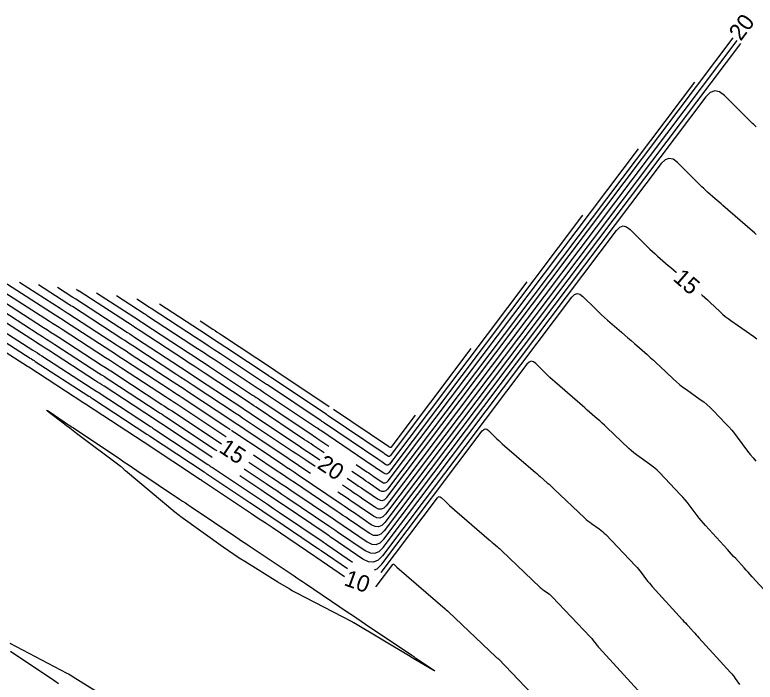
# Model space of a CAD drawing. Extents: x 1797789 to 1803805, y 249066 to 250293.
# Drawn here: x 1798010.2 to 1798279.1, y 250027.1 to 250269.4 of the extents above; entities that cross this region are included whole.
import ezdxf

# ---------------------------------------------------------------- set-up
doc = ezdxf.new("R2010")
doc.units = 0
doc.layers.add('33', color=7, linetype='Continuous')
doc.layers.add('34', color=7, linetype='Continuous')

msp = doc.modelspace()

# ---------------------------------------------------------------- linework, layer by layer
at = {"layer": '33'}
for points in [[(1798130.87, 250101.08), (1798134.09, 250098.91), (1798135.07, 250098.25), (1798136.05, 250097.58), (1798137.03, 250096.91), (1798138.01, 250096.25), (1798141.93, 250093.57), (1798142.88, 250093.11), (1798143.76, 250093.04), (1798144.57, 250093.38), (1798145.32, 250094.13), (1798271.14, 250260.98)], [(1798095.22, 250106.98), (1798103.53, 250101.42), (1798105.25, 250100.27), (1798106.97, 250099.12), (1798108.69, 250097.96), (1798110.41, 250096.8), (1798125.95, 250086.31), (1798126.82, 250085.72), (1798127.69, 250085.13), (1798128.56, 250084.54), (1798129.43, 250083.94), (1798138.14, 250078), (1798139.82, 250077.17), (1798141.39, 250077.06), (1798142.83, 250077.67), (1798144.16, 250078.99), (1798228.7, 250191.09), (1798229.87, 250192.25), (1798231.09, 250192.7), (1798232.36, 250192.43), (1798233.68, 250191.44), (1798239.95, 250185.17), (1798240.85, 250184.28), (1798241.78, 250183.41), (1798242.71, 250182.55), (1798243.66, 250181.72), (1798247.5, 250178.4), (1798248.46, 250177.57), (1798249.42, 250176.74), (1798250.38, 250175.9), (1798250.53, 250175.77)], [(1797989.59, 250175.67), (1798000.85, 250168.54), (1798001.61, 250168.05), (1798002.37, 250167.57), (1798003.13, 250167.08), (1798003.89, 250166.6), (1798020.62, 250155.88), (1798022.02, 250154.98), (1798023.42, 250154.08), (1798024.82, 250153.18), (1798026.22, 250152.27), (1798041.96, 250142.08), (1798043.19, 250141.29), (1798044.41, 250140.49), (1798045.64, 250139.69), (1798046.86, 250138.89), (1798063.61, 250127.93), (1798064.47, 250127.36), (1798065.33, 250126.8), (1798066.19, 250126.23), (1798067.05, 250125.67), (1798084.43, 250114.17), (1798085.23, 250113.64)], [(1798025.68, 250170.44), (1798031.26, 250166.87), (1798031.52, 250166.7), (1798031.79, 250166.53), (1798032.05, 250166.36), (1798032.32, 250166.19), (1798051.11, 250154.02), (1798051.94, 250153.48), (1798052.77, 250152.94), (1798053.6, 250152.4), (1798054.43, 250151.86), (1798070.42, 250141.4), (1798072.05, 250140.33), (1798073.69, 250139.25), (1798075.33, 250138.17), (1798076.96, 250137.09), (1798092.6, 250126.75), (1798093.58, 250126.11), (1798094.55, 250125.46), (1798095.52, 250124.82), (1798096.49, 250124.17), (1798113.46, 250112.83), (1798114.4, 250112.2), (1798115.33, 250111.57), (1798116.27, 250110.94), (1798117.21, 250110.31), (1798120.93, 250107.8)], [(1798259.56, 250167.87), (1798259.87, 250167.6), (1798260.81, 250166.75), (1798261.74, 250165.89), (1798262.66, 250165.03), (1798266.33, 250161.54), (1798267.26, 250160.69), (1798268.22, 250159.87), (1798269.21, 250159.09), (1798270.24, 250158.35), (1798278.62, 250152.51), (1798279.62, 250151.77)], [(1798175.84, 250148.21), (1798146.48, 250109.27), (1798146.31, 250109.1), (1798146.13, 250109.03), (1798145.93, 250109.04), (1798145.72, 250109.14), (1798144.85, 250109.74), (1798144.63, 250109.89), (1798144.41, 250110.04), (1798144.2, 250110.18), (1798143.98, 250110.33), (1798124, 250123.82), (1798123.85, 250123.92), (1798123.7, 250124.03), (1798123.54, 250124.13), (1798123.39, 250124.23), (1798103.3, 250137.66), (1798103.1, 250137.79), (1798102.91, 250137.92), (1798102.71, 250138.05), (1798102.52, 250138.18), (1798086.86, 250148.53), (1798084.46, 250150.12), (1798082.05, 250151.7), (1798079.65, 250153.28), (1798077.24, 250154.86), (1798062.79, 250164.32)], [(1797994.16, 250155.02), (1798014.86, 250141.76), (1798014.96, 250141.69), (1798015.06, 250141.63), (1798015.16, 250141.56), (1798015.26, 250141.5), (1798035.29, 250128.53), (1798035.86, 250128.16), (1798035.96, 250128.1), (1798036.05, 250128.04), (1798036.15, 250127.98), (1798036.24, 250127.91), (1798056.81, 250114.45), (1798056.89, 250114.4), (1798056.97, 250114.35), (1798057.05, 250114.29), (1798057.13, 250114.24), (1798077.64, 250100.68), (1798077.73, 250100.62), (1798077.83, 250100.56), (1798077.92, 250100.5), (1798078.01, 250100.44), (1798093.6, 250090.02), (1798096.1, 250088.34), (1798098.61, 250086.66), (1798101.11, 250084.98), (1798103.61, 250083.29), (1798119.15, 250072.8), (1798119.24, 250072.74), (1798119.33, 250072.68), (1798119.42, 250072.62), (1798119.51, 250072.55), (1798129.96, 250065.42)], [(1798141.38, 250061.72), (1798141.44, 250061.77), (1798147.47, 250069.77), (1798147.58, 250069.88), (1798147.69, 250069.92), (1798147.81, 250069.89), (1798147.93, 250069.8), (1798148.43, 250069.3), (1798148.56, 250069.18), (1798148.69, 250069.05), (1798148.82, 250068.93), (1798148.95, 250068.82), (1798166.46, 250053.69), (1798166.57, 250053.6), (1798166.68, 250053.5), (1798166.79, 250053.41), (1798166.9, 250053.31), (1798167.33, 250052.93), (1798167.44, 250052.84), (1798167.55, 250052.74), (1798167.65, 250052.64), (1798167.76, 250052.55), (1798184.95, 250036.21), (1798185.02, 250036.14), (1798185.1, 250036.08), (1798185.17, 250036.02), (1798185.25, 250035.96), (1798185.57, 250035.74), (1798185.65, 250035.68), (1798185.72, 250035.62), (1798185.79, 250035.56), (1798185.86, 250035.49), (1798202.79, 250017.7)]]:
    msp.add_lwpolyline(points, dxfattribs=at)
at = {"layer": '34'}
for points in [[(1798272.45, 250259.99), (1798145.09, 250091.1), (1798144.22, 250090.24), (1798143.28, 250089.85), (1798142.27, 250089.92), (1798141.17, 250090.46), (1798136.65, 250093.55), (1798135.51, 250094.32), (1798134.38, 250095.09), (1798133.24, 250095.86), (1798132.11, 250096.63), (1798129.19, 250098.6)], [(1798273.75, 250259), (1798144.86, 250088.07), (1798143.88, 250087.1), (1798142.81, 250086.65), (1798141.66, 250086.73), (1798140.42, 250087.34), (1798135.28, 250090.85), (1798133.99, 250091.72), (1798132.71, 250092.6), (1798131.42, 250093.47), (1798130.13, 250094.34), (1798127.51, 250096.11)], [(1798257, 250244.95), (1798145.55, 250097.16), (1798144.92, 250096.53), (1798144.23, 250096.24), (1798143.49, 250096.29), (1798142.69, 250096.69), (1798139.38, 250098.94), (1798138.55, 250099.51), (1798137.72, 250100.07), (1798136.9, 250100.63), (1798136.07, 250101.2), (1798132.55, 250103.57)], [(1798279.42, 250228.72), (1798278.98, 250229.12), (1798278.56, 250229.52), (1798278.14, 250229.93), (1798267.97, 250240.1), (1798266.18, 250241.44), (1798264.45, 250241.81), (1798262.78, 250241.2), (1798261.19, 250239.62), (1798144.63, 250085.05), (1798143.53, 250083.95), (1798142.34, 250083.45), (1798141.05, 250083.55), (1798139.66, 250084.23), (1798133.4, 250088.5), (1798132.22, 250089.3), (1798131.03, 250090.11), (1798129.85, 250090.91), (1798128.67, 250091.71), (1798113.13, 250102.2), (1798111.72, 250103.15), (1798110.32, 250104.1), (1798108.91, 250105.04), (1798107.5, 250105.99), (1798098.55, 250111.97)], [(1798134.23, 250106.06), (1798138.04, 250103.48), (1798138.72, 250103.02), (1798139.4, 250102.56), (1798140.07, 250102.1), (1798140.75, 250101.64), (1798143.45, 250099.8), (1798144.1, 250099.48), (1798144.71, 250099.44), (1798145.27, 250099.67), (1798145.78, 250100.18), (1798236.71, 250220.76)], [(1798279.47, 250189.56), (1798278.79, 250190.17), (1798278.11, 250190.78), (1798267.37, 250200.17), (1798266.67, 250200.78), (1798265.97, 250201.39), (1798265.27, 250201.99), (1798264.57, 250202.6), (1798261.76, 250205.03), (1798261.06, 250205.64), (1798260.38, 250206.26), (1798259.71, 250206.9), (1798259.04, 250207.55), (1798250.83, 250215.77), (1798249.27, 250216.93), (1798247.77, 250217.25), (1798246.33, 250216.73), (1798244.94, 250215.36), (1798144.39, 250082.02), (1798143.18, 250080.81), (1798141.86, 250080.26), (1798140.43, 250080.36), (1798138.9, 250081.11), (1798131.41, 250086.22), (1798130.39, 250086.92), (1798129.36, 250087.62), (1798128.34, 250088.31), (1798127.31, 250089.01), (1798111.77, 250099.5), (1798110.21, 250100.56), (1798108.64, 250101.61), (1798107.08, 250102.66), (1798105.51, 250103.7), (1798096.88, 250109.47)], [(1798216.42, 250196.58), (1798146.01, 250103.21), (1798145.62, 250102.82), (1798145.18, 250102.63), (1798144.71, 250102.67), (1798144.21, 250102.92), (1798142.12, 250104.34), (1798141.59, 250104.7), (1798141.07, 250105.05), (1798140.55, 250105.41), (1798140.02, 250105.76), (1798121.29, 250118.42), (1798120.82, 250118.73), (1798120.35, 250119.04), (1798119.88, 250119.36), (1798119.41, 250119.67), (1798100.57, 250132.26), (1798100.07, 250132.6), (1798099.56, 250132.94), (1798099.06, 250133.27), (1798098.55, 250133.61), (1798082.91, 250143.95), (1798080.81, 250145.34), (1798078.71, 250146.72), (1798076.6, 250148.1), (1798074.5, 250149.48), (1798058.43, 250160), (1798058.11, 250160.21), (1798057.79, 250160.42), (1798057.47, 250160.62), (1798057.15, 250160.83), (1798047.18, 250167.29)], [(1797981.95, 250176.97), (1797998.46, 250166.5), (1797999.58, 250165.79), (1798000.7, 250165.08), (1798001.81, 250164.37), (1798002.92, 250163.65), (1798018.72, 250153.54), (1798020.23, 250152.56), (1798021.75, 250151.59), (1798023.27, 250150.61), (1798024.78, 250149.63), (1798040.74, 250139.3), (1798041.74, 250138.65), (1798042.74, 250138), (1798043.74, 250137.35), (1798044.74, 250136.69), (1798062.25, 250125.23), (1798062.96, 250124.77), (1798063.66, 250124.31), (1798064.36, 250123.85), (1798065.07, 250123.38), (1798083.07, 250111.47), (1798083.57, 250111.15)], [(1798086.9, 250116.14), (1798086.82, 250116.19), (1798085.79, 250116.87), (1798069.03, 250127.95), (1798068.02, 250128.62), (1798067, 250129.29), (1798065.99, 250129.96), (1798064.97, 250130.62), (1798048.98, 250141.09), (1798047.53, 250142.03), (1798046.08, 250142.98), (1798044.63, 250143.92), (1798043.18, 250144.86), (1798027.44, 250155.06), (1798026.27, 250155.81), (1798025.1, 250156.57), (1798023.92, 250157.32), (1798022.75, 250158.07), (1798004.85, 250169.54), (1798004.45, 250169.8), (1798004.04, 250170.06), (1798003.64, 250170.32), (1798003.23, 250170.57), (1797997.24, 250174.38)], [(1798088.57, 250118.63), (1798088.34, 250118.78), (1798087.15, 250119.57), (1798071.02, 250130.24), (1798069.85, 250131.01), (1798068.68, 250131.78), (1798067.51, 250132.55), (1798066.33, 250133.32), (1798050.43, 250143.72), (1798049.09, 250144.6), (1798047.76, 250145.47), (1798046.42, 250146.34), (1798045.07, 250147.21), (1798028.66, 250157.84), (1798027.71, 250158.45), (1798026.77, 250159.06), (1798025.82, 250159.67), (1798024.88, 250160.27), (1798005.81, 250172.49), (1798005.76, 250172.52), (1798005.71, 250172.55), (1798005.67, 250172.58), (1798005.62, 250172.61), (1798004.88, 250173.08)], [(1798117.57, 250102.83), (1798114.49, 250104.91), (1798113.24, 250105.75), (1798111.99, 250106.59), (1798110.74, 250107.43), (1798109.48, 250108.27), (1798093.76, 250118.77), (1798092.48, 250119.63), (1798091.2, 250120.48), (1798089.92, 250121.33), (1798088.64, 250122.18), (1798073, 250132.52), (1798071.67, 250133.4), (1798070.35, 250134.27), (1798069.02, 250135.14), (1798067.69, 250136.01), (1798051.77, 250146.44), (1798050.6, 250147.2), (1798049.43, 250147.96), (1798048.26, 250148.72), (1798047.09, 250149.48), (1798029.88, 250160.62), (1798029.16, 250161.09), (1798028.44, 250161.55), (1798027.72, 250162.01), (1798027, 250162.47), (1798011.88, 250172.16)], [(1798119.25, 250105.31), (1798115.85, 250107.61), (1798114.75, 250108.35), (1798113.66, 250109.08), (1798112.57, 250109.81), (1798111.47, 250110.55), (1798095.12, 250121.47), (1798094, 250122.22), (1798092.87, 250122.97), (1798091.75, 250123.72), (1798090.62, 250124.46), (1798074.98, 250134.81), (1798073.5, 250135.78), (1798072.02, 250136.76), (1798070.54, 250137.73), (1798069.06, 250138.71), (1798053.1, 250149.15), (1798052.1, 250149.8), (1798051.1, 250150.45), (1798050.1, 250151.1), (1798049.1, 250151.75), (1798031.1, 250163.41), (1798030.6, 250163.73), (1798030.11, 250164.04), (1798029.62, 250164.36), (1798029.13, 250164.67), (1798018.78, 250171.3)], [(1798196.13, 250172.39), (1798146.25, 250106.24), (1798145.96, 250105.96), (1798145.66, 250105.83), (1798145.32, 250105.85), (1798144.96, 250106.03), (1798143.48, 250107.04), (1798143.11, 250107.29), (1798142.74, 250107.55), (1798142.37, 250107.8), (1798142, 250108.05), (1798122.65, 250121.12), (1798122.33, 250121.33), (1798122.02, 250121.54), (1798121.71, 250121.74), (1798121.4, 250121.95), (1798101.94, 250134.96), (1798101.59, 250135.19), (1798101.24, 250135.43), (1798100.89, 250135.66), (1798100.54, 250135.89), (1798084.9, 250146.23), (1798082.64, 250147.72), (1798080.38, 250149.21), (1798078.12, 250150.7), (1798075.86, 250152.18), (1798059.76, 250162.71), (1798059.61, 250162.81), (1798059.46, 250162.91), (1798059.31, 250163), (1798059.17, 250163.1), (1798054.52, 250166.11)], [(1798122.6, 250110.28), (1798118.57, 250113.01), (1798117.79, 250113.54), (1798117.01, 250114.06), (1798116.22, 250114.59), (1798115.44, 250115.11), (1798097.85, 250126.87), (1798097.03, 250127.41), (1798096.22, 250127.95), (1798095.4, 250128.49), (1798094.59, 250129.04), (1798078.95, 250139.38), (1798077.16, 250140.56), (1798075.36, 250141.74), (1798073.57, 250142.92), (1798071.78, 250144.1), (1798055.76, 250154.57), (1798055.1, 250155), (1798054.45, 250155.43), (1798053.79, 250155.86), (1798053.13, 250156.29), (1798033.53, 250168.98), (1798033.5, 250169), (1798033.46, 250169.02), (1798033.42, 250169.05), (1798033.38, 250169.07), (1798032.58, 250169.59)], [(1798039.85, 250168.46), (1798055.14, 250158.56), (1798055.63, 250158.24), (1798056.12, 250157.92), (1798056.61, 250157.61), (1798057.1, 250157.29), (1798073.14, 250146.79), (1798075.09, 250145.51), (1798077.04, 250144.23), (1798078.98, 250142.95), (1798080.93, 250141.66), (1798096.57, 250131.32), (1798097.23, 250130.88), (1798097.89, 250130.44), (1798098.55, 250130), (1798099.21, 250129.56), (1798117.43, 250117.39), (1798118.05, 250116.97), (1798118.68, 250116.55), (1798119.3, 250116.13), (1798119.93, 250115.71), (1798124.28, 250112.77)], [(1798093.55, 250104.48), (1798101.54, 250099.14), (1798103.42, 250097.88), (1798105.3, 250096.63), (1798107.17, 250095.36), (1798109.05, 250094.1), (1798124.59, 250083.61), (1798125.3, 250083.12), (1798126.02, 250082.64), (1798126.73, 250082.15), (1798127.45, 250081.67), (1798137.38, 250074.89), (1798139.21, 250073.98), (1798140.91, 250073.86), (1798142.49, 250074.52), (1798143.93, 250075.96), (1798212.45, 250166.83), (1798213.41, 250167.78), (1798214.41, 250168.14), (1798215.45, 250167.92), (1798216.53, 250167.11), (1798220.93, 250162.71), (1798222.04, 250161.62), (1798223.17, 250160.55), (1798224.32, 250159.5), (1798225.49, 250158.47), (1798230.54, 250154.11), (1798231.71, 250153.1), (1798232.87, 250152.09), (1798234.04, 250151.08), (1798235.2, 250150.06), (1798239.85, 250146), (1798241, 250144.97), (1798242.15, 250143.94), (1798243.28, 250142.89), (1798244.41, 250141.84), (1798249.31, 250137.18), (1798250.45, 250136.14), (1798251.62, 250135.14), (1798252.83, 250134.19), (1798254.08, 250133.29), (1798259.15, 250129.75), (1798260.39, 250128.84), (1798261.58, 250127.87), (1798262.72, 250126.84), (1798263.81, 250125.75), (1798268.42, 250120.9), (1798269.5, 250119.73), (1798270.54, 250118.54), (1798271.55, 250117.31), (1798272.52, 250116.06), (1798276.33, 250110.98), (1798277.3, 250109.72), (1798278.3, 250108.49), (1798279.33, 250107.28)], [(1798081.9, 250108.65), (1798081.72, 250108.77), (1798063.08, 250121.1), (1798062.54, 250121.46), (1798061.99, 250121.82), (1798061.44, 250122.18), (1798060.89, 250122.54), (1798042.61, 250134.5), (1798041.84, 250135), (1798041.07, 250135.51), (1798040.29, 250136.01), (1798039.52, 250136.51), (1798022.4, 250147.6), (1798021.24, 250148.35), (1798020.08, 250149.1), (1798018.92, 250149.84), (1798017.75, 250150.59), (1798001.96, 250160.71)], [(1798000.34, 250158.18), (1798016.79, 250147.65), (1798017.6, 250147.13), (1798018.41, 250146.61), (1798019.22, 250146.09), (1798020.02, 250145.56), (1798038.3, 250133.73), (1798038.85, 250133.37), (1798039.4, 250133.02), (1798039.94, 250132.66), (1798040.49, 250132.3), (1798059.53, 250119.84), (1798059.92, 250119.59), (1798060.32, 250119.33), (1798060.71, 250119.07), (1798061.1, 250118.81), (1798080.36, 250106.08), (1798080.76, 250105.81), (1798081.17, 250105.54), (1798081.57, 250105.27), (1798081.98, 250105), (1798097.57, 250094.58), (1798099.76, 250093.11), (1798101.95, 250091.64), (1798104.14, 250090.17), (1798106.33, 250088.7), (1798121.87, 250078.2), (1798122.27, 250077.93), (1798122.67, 250077.66), (1798123.08, 250077.38), (1798123.48, 250077.11), (1798132.89, 250070.69)], [(1798077.46, 250158.3), (1798082.16, 250155.22), (1798082.95, 250154.71), (1798083.73, 250154.2), (1798084.51, 250153.68), (1798085.29, 250153.17), (1798104.5, 250140.46), (1798104.54, 250140.43), (1798104.58, 250140.41), (1798104.62, 250140.38), (1798104.66, 250140.36), (1798124.37, 250127.19)], [(1797997.25, 250156.6), (1798015.83, 250144.7), (1798016.28, 250144.41), (1798016.74, 250144.12), (1798017.19, 250143.82), (1798017.64, 250143.53), (1798037.08, 250130.95), (1798037.4, 250130.74), (1798037.72, 250130.53), (1798038.05, 250130.32), (1798038.37, 250130.11), (1798058.17, 250117.15), (1798058.41, 250116.99), (1798058.64, 250116.84), (1798058.88, 250116.68), (1798059.12, 250116.53), (1798079, 250103.38), (1798079.25, 250103.21), (1798079.5, 250103.05), (1798079.75, 250102.88), (1798079.99, 250102.72), (1798095.58, 250092.3), (1798097.93, 250090.73), (1798100.28, 250089.15), (1798102.63, 250087.57), (1798104.97, 250085.99), (1798120.51, 250075.5), (1798120.76, 250075.33), (1798121, 250075.17), (1798121.25, 250075), (1798121.49, 250074.83), (1798131.01, 250068.34)], [(1798286.35, 250056.18), (1798278.04, 250065.29), (1798277.28, 250066.12), (1798276.53, 250066.95), (1798275.77, 250067.77), (1798275.02, 250068.6), (1798272, 250071.91), (1798271.24, 250072.74), (1798270.49, 250073.57), (1798269.74, 250074.4), (1798268.98, 250075.22), (1798261.05, 250083.92), (1798260.25, 250084.81), (1798259.47, 250085.73), (1798258.72, 250086.66), (1798257.99, 250087.61), (1798255.11, 250091.44), (1798254.38, 250092.39), (1798253.61, 250093.32), (1798252.83, 250094.22), (1798252.01, 250095.1), (1798244.32, 250103.18), (1798243.49, 250104.02), (1798242.61, 250104.81), (1798241.7, 250105.55), (1798240.75, 250106.25), (1798236.87, 250108.96), (1798235.92, 250109.65), (1798234.99, 250110.38), (1798234.09, 250111.14), (1798233.22, 250111.94), (1798225.25, 250119.51), (1798224.38, 250120.33), (1798223.5, 250121.14), (1798222.61, 250121.94), (1798221.72, 250122.73), (1798218.12, 250125.87), (1798217.22, 250126.66), (1798216.32, 250127.44), (1798215.42, 250128.22), (1798214.52, 250129), (1798206.35, 250136.06), (1798205.44, 250136.86), (1798204.55, 250137.68), (1798203.67, 250138.51), (1798202.81, 250139.36), (1798199.38, 250142.78), (1798198.54, 250143.41), (1798197.73, 250143.59), (1798196.95, 250143.3), (1798196.21, 250142.56), (1798143.7, 250072.94), (1798142.14, 250071.38), (1798140.44, 250070.67), (1798138.6, 250070.8), (1798136.62, 250071.77), (1798125.46, 250079.39), (1798124.9, 250079.77), (1798124.35, 250080.15), (1798123.79, 250080.53), (1798123.23, 250080.9), (1798107.69, 250091.4), (1798105.66, 250092.77), (1798103.63, 250094.13), (1798101.59, 250095.5), (1798099.56, 250096.86), (1798091.88, 250101.99)], [(1798155.55, 250124.02), (1798146.71, 250112.3), (1798146.66, 250112.25), (1798146.6, 250112.22), (1798146.54, 250112.23), (1798146.48, 250112.26), (1798146.22, 250112.44), (1798146.15, 250112.48), (1798146.09, 250112.53), (1798146.02, 250112.57), (1798145.96, 250112.62), (1798125.98, 250126.11)], [(1798098.53, 250111.98), (1798091.91, 250116.4), (1798090.72, 250117.2), (1798089.53, 250117.99), (1798088.85, 250118.44)], [(1798140.83, 250067.83), (1798141.79, 250068.24), (1798143.47, 250069.91), (1798179.96, 250118.3), (1798180.49, 250118.83), (1798181.05, 250119.03), (1798181.63, 250118.91), (1798182.23, 250118.46), (1798184.68, 250116), (1798185.3, 250115.4), (1798185.93, 250114.8), (1798186.57, 250114.22), (1798187.22, 250113.65), (1798198.5, 250103.9), (1798199.14, 250103.35), (1798199.78, 250102.8), (1798200.41, 250102.24), (1798201.05, 250101.69), (1798203.59, 250099.46), (1798204.22, 250098.91), (1798204.85, 250098.34), (1798205.47, 250097.77), (1798206.08, 250097.19), (1798217.13, 250086.69), (1798217.73, 250086.14), (1798218.36, 250085.61), (1798219, 250085.11), (1798219.67, 250084.62), (1798222.36, 250082.75), (1798223.02, 250082.26), (1798223.65, 250081.75), (1798224.26, 250081.2), (1798224.84, 250080.62), (1798235.61, 250069.3), (1798236.16, 250068.7), (1798236.69, 250068.09), (1798237.2, 250067.47), (1798237.7, 250066.83), (1798239.64, 250064.24), (1798240.14, 250063.59), (1798240.65, 250062.96), (1798241.17, 250062.35), (1798241.71, 250061.74), (1798252.73, 250049.67), (1798253.22, 250049.13), (1798253.72, 250048.58), (1798254.21, 250048.04), (1798254.7, 250047.5), (1798256.67, 250045.34), (1798257.17, 250044.8), (1798257.66, 250044.26), (1798258.15, 250043.72), (1798258.64, 250043.18), (1798270.13, 250030.59), (1798270.59, 250030.07), (1798271.03, 250029.54), (1798271.45, 250029), (1798271.85, 250028.44), (1798273.42, 250026.17)], [(1798143.24, 250066.89), (1798163.71, 250094.03), (1798164.03, 250094.35), (1798164.37, 250094.47), (1798164.72, 250094.4), (1798165.08, 250094.13), (1798166.56, 250092.65), (1798166.93, 250092.29), (1798167.31, 250091.93), (1798167.69, 250091.58), (1798168.08, 250091.23), (1798182.48, 250078.79), (1798182.86, 250078.47), (1798183.23, 250078.15), (1798183.6, 250077.82), (1798183.97, 250077.5), (1798185.46, 250076.2), (1798185.83, 250075.87), (1798186.2, 250075.54), (1798186.56, 250075.21), (1798186.92, 250074.87), (1798201.04, 250061.45), (1798201.38, 250061.14), (1798201.73, 250060.84), (1798202.09, 250060.56), (1798202.46, 250060.29), (1798203.96, 250059.24), (1798204.33, 250058.97), (1798204.69, 250058.68), (1798205.02, 250058.38), (1798205.35, 250058.05), (1798219.2, 250043.5), (1798219.48, 250043.19), (1798219.76, 250042.87), (1798220.03, 250042.55), (1798220.29, 250042.21), (1798221.3, 250040.86), (1798221.56, 250040.53), (1798221.82, 250040.2), (1798222.09, 250039.88), (1798222.37, 250039.57), (1798236.48, 250024.11)], [(1798008.42, 250041.28), (1798029.08, 250030.38), (1798029.68, 250030.06), (1798030.27, 250029.73), (1798030.86, 250029.39), (1798031.44, 250029.03), (1798051.11, 250016.75)], [(1798026.11, 250026.5), (1798024.73, 250027.43), (1798008.69, 250038.21)]]:
    msp.add_lwpolyline(points, dxfattribs=at)
msp.add_lwpolyline([(1798109.66, 250061.02), (1798105.75, 250063.43), (1798093.68, 250070.85), (1798091.68, 250072.11), (1798089.7, 250073.4), (1798087.75, 250074.72), (1798085.82, 250076.08), (1798070.46, 250087.15), (1798069.91, 250087.55), (1798069.37, 250087.96), (1798068.84, 250088.39), (1798068.32, 250088.82), (1798050.41, 250103.81), (1798050.24, 250103.95), (1798050.09, 250104.09), (1798049.93, 250104.23), (1798049.78, 250104.38), (1798049.17, 250104.97), (1798049.01, 250105.11), (1798048.85, 250105.25), (1798048.69, 250105.39), (1798048.52, 250105.51), (1798032.59, 250117.39), (1798031.36, 250118.31), (1798030.14, 250119.23), (1798028.92, 250120.17), (1798027.71, 250121.1), (1798022.86, 250124.87), (1798021.96, 250125.59), (1798021.69, 250125.85), (1798022.03, 250125.68), (1798022.99, 250125.05), (1798029.74, 250120.53), (1798030.18, 250120.24), (1798030.62, 250119.95), (1798031.06, 250119.65), (1798031.5, 250119.36), (1798048.29, 250108.11), (1798049.84, 250107.08), (1798051.39, 250106.04), (1798052.94, 250105), (1798054.49, 250103.96), (1798070.07, 250093.52), (1798071.11, 250092.82), (1798072.16, 250092.12), (1798073.21, 250091.42), (1798074.25, 250090.72), (1798090.5, 250079.81), (1798091.71, 250079), (1798092.92, 250078.19), (1798094.13, 250077.38), (1798095.33, 250076.57), (1798111.63, 250065.62), (1798112.65, 250064.93), (1798113.67, 250064.25), (1798114.69, 250063.56), (1798115.71, 250062.88), (1798131.27, 250052.41), (1798132.84, 250051.35), (1798134.41, 250050.29), (1798135.99, 250049.23), (1798137.56, 250048.17), (1798154.42, 250036.82), (1798154.79, 250036.58), (1798155.15, 250036.33), (1798155.52, 250036.08), (1798155.88, 250035.84), (1798162.23, 250031.56), (1798162.63, 250031.28), (1798162.75, 250031.18), (1798162.6, 250031.24), (1798162.17, 250031.48), (1798155.76, 250035.15), (1798155.25, 250035.44), (1798154.75, 250035.74), (1798154.25, 250036.03), (1798153.75, 250036.33), (1798133.31, 250048.58), (1798133.3, 250048.59), (1798133.28, 250048.6), (1798133.26, 250048.61), (1798133.25, 250048.62), (1798132.92, 250048.83), (1798132.88, 250048.85), (1798132.84, 250048.88), (1798132.8, 250048.9), (1798132.76, 250048.92), (1798112.33, 250059.52), (1798111.65, 250059.88), (1798110.98, 250060.25), (1798110.32, 250060.63)], close=True, dxfattribs=at)

# ---------------------------------------------------------------- texts
at = {"layer": '33'}
for s, rotation, p in [('20', 52.9803, (1798273.83, 250259.57)), ('15', 318.8123, (1798248.94, 250173.18)), ('15', 326.276, (1798083.99, 250110.86)), ('20', 325.9703, (1798119.66, 250105.03)), ('10', 340.2164, (1798129.4, 250062.38))]:
    msp.add_text(s, height=6, rotation=rotation, dxfattribs=at).set_placement(p)

doc.saveas('drawing.dxf')
